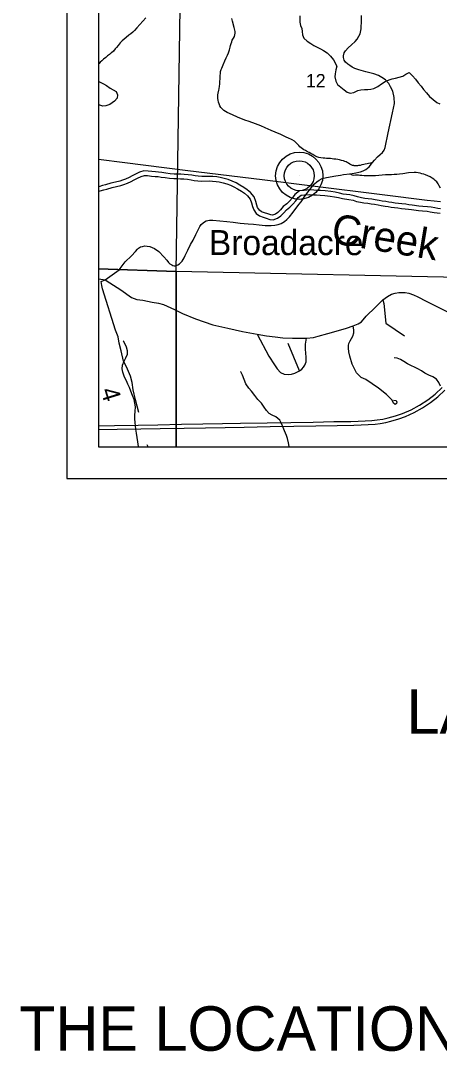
# Model space of a CAD drawing. Extents: x -19 to 40.8, y -1.8 to 26.1.
# Drawn here: x 1.854 to 3.175, y 12.195 to 15.443 of the extents above; entities that cross this region are included whole.
import ezdxf

# ---------------------------------------------------------------- set-up
doc = ezdxf.new("R2010")
doc.units = 0
for name, color, linetype in [('Default', 7, 'Continuous'), ('GM_X_Corporation', 7, 'Continuous'), ('GM_X_Corporation_Text', 7, 'Continuous'), ('GM_X_Interchange_Ramps', 7, 'Continuous'), ('GM_X_Major_River', 7, 'Continuous'), ('GM_X_Minor_River', 7, 'Continuous'), ('GM_X_Rail_Line', 7, 'Continuous'), ('GM_X_Section', 7, 'Continuous'), ('GM_X_Section_Text', 7, 'Continuous'), ('GM_X_State_Route', 7, 'Continuous'), ('GM_X_Township_Road', 7, 'Continuous'), ('GM_X_Township_Road_Text', 7, 'Continuous'), ('GM_X_Unincorporated', 7, 'Continuous'), ('RW_P_Text', 7, 'Continuous'), ('SH_Data', 7, 'Continuous'), ('SH_Text', 7, 'Continuous')]:
    doc.layers.add(name, color=color, linetype=linetype)

msp = doc.modelspace()

# ---------------------------------------------------------------- linework, layer by layer
at = {"layer": 'Default'}
for points in [[(2.1, 15.9023), (2.1, 14.6614), (2.3446, 14.653), (2.3634, 15.8992)], [(2.1, 14.6614), (2.1, 14.1), (2.3441, 14.1), (2.3446, 14.653)], [(2.3441, 14.1), (3.3277, 14.1), (3.3355, 14.6314), (2.3446, 14.653)]]:
    msp.add_lwpolyline(points, close=True, dxfattribs=at)
at = {"layer": 'GM_X_Corporation'}
for points in [[(2.121, 14.6264), (2.1357, 14.6167), (2.17, 14.5947), (2.2039, 14.5709), (2.2208, 14.5646), (2.2394, 14.5617), (2.2688, 14.5555), (2.2883, 14.5526), (2.304, 14.5485), (2.3396, 14.5331), (2.364, 14.5199), (2.4051, 14.5034), (2.4596, 14.484), (2.5077, 14.4735), (2.5535, 14.464), (2.5999, 14.4547), (2.6298, 14.4503), (2.6563, 14.4467), (2.6809, 14.4438), (2.7117, 14.4425), (2.7398, 14.4421), (2.7556, 14.4429), (2.7779, 14.4447), (2.7924, 14.4485), (2.8226, 14.457), (2.8418, 14.4629), (2.8817, 14.4737), (2.9029, 14.4813), (2.9188, 14.4872), (2.9294, 14.4941), (2.944, 14.5115), (2.973, 14.5401), (2.9958, 14.563), (3.0106, 14.5741), (3.0239, 14.5811), (3.0352, 14.5841), (3.0467, 14.5865), (3.0569, 14.5868), (3.0664, 14.5863), (3.0782, 14.5839), (3.0926, 14.5791), (3.1067, 14.5725), (3.1327, 14.5595)], [(3.1327, 14.5595), (3.1497, 14.5509), (3.1941, 14.5287), (3.2186, 14.5153), (3.2302, 14.5078), (3.2401, 14.5), (3.259, 14.4832), (3.2832, 14.4611), (3.3009, 14.4443), (3.314, 14.4321), (3.3181, 14.4282)]]:
    msp.add_lwpolyline(points, dxfattribs=at)
at = {"layer": 'GM_X_Interchange_Ramps'}
msp.add_lwpolyline([(3.1777, 14.8723), (3.1582, 14.8739), (3.1359, 14.8761), (2.9942, 14.8937), (2.7743, 14.9212), (2.624, 14.9399), (2.3727, 14.9713), (2.1822, 14.9952), (2.1, 15.0054)], dxfattribs=at)
at = {"layer": 'GM_X_Major_River'}
msp.add_line((2.7326, 14.9543), (2.7326, 14.9543), dxfattribs=at)
at = {"layer": 'GM_X_Rail_Line'}
for points in [[(2.9636, 14.9961), (2.9697, 15.0038), (2.9791, 15.0139), (2.9879, 15.0215), (2.995, 15.0271), (3.0008, 15.0349), (3.0036, 15.043), (3.0134, 15.0892), (3.0266, 15.1524), (3.0329, 15.1816), (3.0318, 15.2011), (3.0273, 15.2206), (3.0205, 15.234), (3.0148, 15.2445), (3.0042, 15.2561), (2.9934, 15.2641), (2.9825, 15.2697), (2.9674, 15.2754), (2.9431, 15.2821), (2.9211, 15.2877), (2.9081, 15.2924), (2.8998, 15.2967), (2.8918, 15.3018), (2.8854, 15.3055), (2.8788, 15.3117), (2.8748, 15.3183), (2.8725, 15.3268), (2.8725, 15.3325), (2.8742, 15.3411), (2.8785, 15.348), (2.8872, 15.3576), (2.8979, 15.3671), (2.9085, 15.3769), (2.9149, 15.3847), (2.9209, 15.3936), (2.9248, 15.4017), (2.9257, 15.4071), (2.9282, 15.4173), (2.9282, 15.4243), (2.9285, 15.4367), (2.9292, 15.4595)], [(2.892, 14.9606), (2.9063, 14.9627), (2.9256, 14.9664), (2.9345, 14.9698), (2.9427, 14.9744), (2.9527, 14.9825), (2.9636, 14.9961)], [(2.7156, 14.8423), (2.7229, 14.8526), (2.731, 14.8641), (2.7382, 14.8726), (2.7507, 14.89), (2.7741, 14.9213), (2.7804, 14.9289), (2.7876, 14.9353), (2.7959, 14.9408), (2.8049, 14.9452), (2.8185, 14.9489), (2.8478, 14.9536), (2.8632, 14.956)], [(2.8632, 14.956), (2.8722, 14.9577), (2.892, 14.9606)], [(2.121, 14.6264), (2.165, 14.6577), (2.1836, 14.6829), (2.2039, 14.7024), (2.2163, 14.7152), (2.2223, 14.7227), (2.226, 14.7261), (2.2323, 14.7298), (2.2383, 14.7318), (2.2453, 14.733), (2.2531, 14.7326), (2.2613, 14.7313), (2.269, 14.7286), (2.2761, 14.7253), (2.2896, 14.7159), (2.3057, 14.6991), (2.315, 14.6884), (2.3201, 14.6811), (2.3248, 14.6764), (2.3305, 14.6734), (2.3344, 14.6718), (2.3383, 14.6708), (2.342, 14.6709), (2.3455, 14.6717), (2.35, 14.6732), (2.3546, 14.6762), (2.3587, 14.6805), (2.3629, 14.6856), (2.3694, 14.6953), (2.3731, 14.7029), (2.3813, 14.72), (2.3902, 14.7376), (2.3977, 14.7514), (2.4061, 14.7693), (2.4128, 14.7821), (2.4191, 14.7944), (2.4236, 14.8004), (2.4294, 14.8059), (2.4336, 14.8093), (2.4391, 14.8118), (2.4442, 14.8135), (2.4497, 14.8144), (2.4601, 14.8145), (2.4818, 14.8122), (2.5044, 14.8098), (2.5244, 14.8081), (2.5461, 14.8052), (2.5714, 14.8028), (2.5882, 14.8015), (2.6062, 14.7998), (2.6251, 14.7978), (2.6437, 14.7972), (2.6558, 14.7983), (2.6658, 14.8005), (2.6754, 14.8041), (2.6864, 14.8106), (2.6935, 14.8162), (2.7022, 14.8246), (2.7139, 14.8399), (2.7156, 14.8423)], [(2.1, 14.6297), (2.1002, 14.6297), (2.121, 14.6264)]]:
    msp.add_lwpolyline(points, dxfattribs=at)
at = {"layer": 'GM_X_Section'}
for points in [[(2.7342, 15.4581), (2.7344, 15.4384), (2.7367, 15.4278), (2.7406, 15.4183), (2.7422, 15.4084), (2.7431, 15.3982), (2.7469, 15.3876), (2.7577, 15.3781), (2.7687, 15.371), (2.7787, 15.3642), (2.789, 15.3594), (2.8, 15.3542), (2.8096, 15.3485), (2.821, 15.3414), (2.8314, 15.3316), (2.8402, 15.3199), (2.8507, 15.2995), (2.8481, 15.288), (2.8455, 15.2755), (2.8449, 15.266), (2.848, 15.2523), (2.853, 15.2417), (2.8641, 15.2334), (2.8741, 15.2252), (2.884, 15.218), (2.8935, 15.2143), (2.9049, 15.2171), (2.917, 15.2232), (2.9273, 15.2252), (2.9383, 15.2264), (2.9485, 15.2258), (2.9584, 15.227), (2.9679, 15.2297), (2.98, 15.2351), (2.9921, 15.244), (3.0038, 15.2517), (3.0159, 15.2567), (3.0254, 15.2594), (3.0364, 15.2618), (3.0477, 15.2646), (3.0591, 15.2684), (3.0693, 15.2742), (3.0795, 15.2793), (3.0895, 15.2687), (3.0991, 15.2581), (3.1079, 15.2472), (3.1171, 15.237), (3.1248, 15.2264), (3.134, 15.2151), (3.1436, 15.2045), (3.1551, 15.1944), (3.1662, 15.1849), (3.1757, 15.1805)], [(2.1, 15.2513), (2.103, 15.2502), (2.1149, 15.2435), (2.1252, 15.2382), (2.1359, 15.2303), (2.1454, 15.2251), (2.1554, 15.2198), (2.1596, 15.2088), (2.1582, 15.1986), (2.1495, 15.189), (2.1348, 15.1786), (2.1223, 15.1743), (2.1128, 15.1739), (2.1033, 15.1765), (2.1, 15.1777)], [(2.9285, 14.885), (2.9167, 14.8874), (2.9062, 14.8907), (2.8917, 14.8938), (2.8713, 14.8967), (2.8591, 14.8995), (2.8461, 14.9022), (2.8321, 14.9045), (2.8147, 14.9063), (2.7999, 14.9074), (2.7881, 14.908), (2.7785, 14.9087), (2.7655, 14.9098), (2.7481, 14.9081), (2.7337, 14.9064), (2.7185, 14.8955), (2.7105, 14.8838), (2.7024, 14.8746), (2.6932, 14.8659), (2.6824, 14.8574), (2.6732, 14.8468), (2.6651, 14.8386), (2.6578, 14.8337), (2.6487, 14.8301), (2.6431, 14.8307), (2.6333, 14.8338), (2.6233, 14.8374), (2.6141, 14.8408), (2.6073, 14.8458), (2.6015, 14.8539), (2.5987, 14.8611), (2.596, 14.8727), (2.5905, 14.8876), (2.5793, 14.9011), (2.5683, 14.9102), (2.5579, 14.9175), (2.5454, 14.9251), (2.5332, 14.9318), (2.5209, 14.9374), (2.5083, 14.9424), (2.4959, 14.9456), (2.4833, 14.9486), (2.4728, 14.9506), (2.4599, 14.9518), (2.4497, 14.9521), (2.4251, 14.9519), (2.4136, 14.9525), (2.4039, 14.9538), (2.3942, 14.9556), (2.3823, 14.9576), (2.3698, 14.9583), (2.3588, 14.9589), (2.3477, 14.9597), (2.3379, 14.9596), (2.3253, 14.9605), (2.3115, 14.9627), (2.2992, 14.964), (2.2891, 14.966), (2.2789, 14.9663), (2.2678, 14.9673), (2.2558, 14.9687), (2.243, 14.9696), (2.2292, 14.9654), (2.2166, 14.9594), (2.2058, 14.9535), (2.1965, 14.9488), (2.1851, 14.9437), (2.1755, 14.9402), (2.1665, 14.9377), (2.1528, 14.9345), (2.1389, 14.9305), (2.1221, 14.9259), (2.1123, 14.9235), (2.1008, 14.9198), (2.1, 14.9195)], [(2.1, 14.9046), (2.1052, 14.9063), (2.1162, 14.9098), (2.1257, 14.9122), (2.1427, 14.9169), (2.1564, 14.9208), (2.17, 14.9239), (2.1799, 14.9267), (2.1905, 14.9305), (2.2026, 14.9359), (2.2124, 14.941), (2.223, 14.9468), (2.2344, 14.9522), (2.2446, 14.9553), (2.2545, 14.9546), (2.2663, 14.9532), (2.2781, 14.9521), (2.2876, 14.9518), (2.2971, 14.95), (2.3096, 14.9486), (2.3237, 14.9464), (2.3374, 14.9454), (2.3473, 14.9455), (2.3579, 14.9448), (2.3689, 14.9441), (2.3807, 14.9434), (2.3917, 14.9416), (2.4016, 14.9398), (2.4123, 14.9384), (2.4248, 14.9377), (2.4495, 14.9379), (2.459, 14.9376), (2.4708, 14.9366), (2.4803, 14.9347), (2.4925, 14.9318), (2.5039, 14.9288), (2.5154, 14.9244), (2.5268, 14.9191), (2.5383, 14.9128), (2.5501, 14.9056), (2.5596, 14.8989), (2.5692, 14.891), (2.578, 14.8804), (2.5823, 14.8687), (2.5851, 14.8569), (2.589, 14.8471), (2.597, 14.8357), (2.6074, 14.8282), (2.6184, 14.8241), (2.6287, 14.8204), (2.6401, 14.8167), (2.6508, 14.8156), (2.6644, 14.8211), (2.6742, 14.8276), (2.6836, 14.8372), (2.6923, 14.8471), (2.7025, 14.8552), (2.7127, 14.8648), (2.7217, 14.8751), (2.7288, 14.8854), (2.739, 14.8927), (2.7496, 14.8939), (2.7656, 14.8956), (2.7774, 14.8945), (2.7873, 14.8939), (2.799, 14.8932), (2.8135, 14.8922), (2.8302, 14.8904), (2.8435, 14.8882), (2.8561, 14.8857), (2.8686, 14.8827), (2.8892, 14.8799), (2.9025, 14.8769), (2.9132, 14.8736), (2.9257, 14.871)], [(3.1781, 14.8504), (3.1695, 14.8513), (3.1604, 14.8527), (3.1482, 14.8549), (3.1376, 14.8564), (3.1221, 14.8575), (3.1101, 14.8588), (3.0887, 14.8617), (3.0785, 14.8628), (3.0683, 14.8642), (3.0565, 14.8656), (3.0457, 14.8671), (3.0347, 14.8681), (3.025, 14.8695), (3.0152, 14.8713), (3.0055, 14.8728), (2.9939, 14.8745), (2.9842, 14.8763), (2.9721, 14.8786), (2.9615, 14.8801), (2.9503, 14.8815), (2.939, 14.8829), (2.9285, 14.885)], [(2.9257, 14.871), (2.9368, 14.8688), (2.9486, 14.8674), (2.9596, 14.866), (2.9699, 14.8645), (2.9817, 14.8624), (2.9915, 14.8605), (3.0033, 14.8587), (3.0128, 14.8573), (3.0227, 14.8555), (3.033, 14.854), (3.044, 14.853), (3.0547, 14.8515), (3.0665, 14.8501), (3.0767, 14.8487), (3.087, 14.8476), (3.1083, 14.8448), (3.1209, 14.8433), (3.1361, 14.8423), (3.146, 14.8409), (3.1581, 14.8387), (3.1676, 14.8372), (3.1771, 14.8362)], [(2.2264, 14.1), (2.2261, 14.1016), (2.224, 14.1157), (2.2216, 14.1297), (2.2193, 14.143), (2.2173, 14.1552), (2.216, 14.1658), (2.2148, 14.1772), (2.2143, 14.1886), (2.2146, 14.2), (2.2153, 14.211), (2.2159, 14.2258), (2.2146, 14.238), (2.2119, 14.249), (2.2065, 14.2618), (2.2014, 14.2759), (2.1971, 14.2865), (2.1917, 14.2975), (2.1875, 14.3084), (2.182, 14.3198), (2.1758, 14.3349), (2.1738, 14.3456), (2.1753, 14.3577), (2.1808, 14.3699), (2.1853, 14.3806), (2.1905, 14.3921), (2.1908, 14.4027), (2.1877, 14.4137), (2.1838, 14.4236), (2.178, 14.4334), (2.1773, 14.4345)], [(3.1784, 14.2909), (3.1734, 14.3026), (3.1657, 14.3128), (3.1542, 14.3211), (3.1416, 14.3259), (3.1286, 14.3327), (3.1179, 14.3394), (3.1069, 14.3462), (3.0962, 14.3514), (3.0867, 14.3555), (3.0745, 14.3611), (3.0622, 14.3686), (3.0519, 14.375), (3.042, 14.3798), (3.0321, 14.3809)], [(2.7011, 14.1), (2.701, 14.1012), (2.6986, 14.113), (2.6958, 14.1259), (2.6927, 14.1357), (2.6865, 14.1501), (2.6818, 14.1611), (2.6768, 14.174), (2.671, 14.1838), (2.6591, 14.1944), (2.6473, 14.2), (2.6374, 14.2048), (2.6289, 14.215), (2.6224, 14.2252), (2.6132, 14.2381), (2.6024, 14.2494), (2.5925, 14.2615), (2.5817, 14.2755), (2.5733, 14.2853), (2.564, 14.2981), (2.5586, 14.3121), (2.5532, 14.3258), (2.5481, 14.3368), (2.5477, 14.3371)]]:
    msp.add_lwpolyline(points, dxfattribs=at)
at = {"layer": 'GM_X_State_Route'}
for p, q in [((2.7338, 14.34), (2.6979, 14.426)), ((2.2559, 14.1), (2.2534, 14.1067))]:
    msp.add_line(p, q, dxfattribs=at)
msp.add_lwpolyline([(2.1, 15.8991), (2.1, 14.1), (4.3215, 14.1), (4.3262, 14.3024), (4.3261, 14.4335), (4.3369, 14.8581), (4.3371, 14.8653), (4.3373, 14.8703), (4.3441, 15.1043), (4.3494, 15.3211), (4.3628, 15.868), (3.9893, 15.872), (3.7032, 15.8784), (3.0926, 15.8861), (2.1833, 15.8974)], close=True, dxfattribs=at)
for points in [[(2.2483, 15.4516), (2.2389, 15.4412), (2.2297, 15.4306), (2.2202, 15.4199), (2.2128, 15.412), (2.2077, 15.4065), (2.2015, 15.4016), (2.1952, 15.397), (2.1864, 15.39), (2.1806, 15.3851), (2.174, 15.379), (2.1683, 15.3726), (2.1615, 15.3649), (2.1567, 15.3586), (2.1521, 15.3537), (2.1464, 15.3471), (2.1406, 15.3418), (2.1386, 15.3402), (2.1372, 15.3391)], [(2.9047, 14.9861), (2.9028, 14.9864), (2.9009, 14.9868), (2.896, 14.9887), (2.8919, 14.991), (2.8875, 14.9934), (2.884, 14.996), (2.8806, 14.9976), (2.8767, 14.9993), (2.8721, 15.0008), (2.8662, 15.0024), (2.8596, 15.0039), (2.8541, 15.0053), (2.8479, 15.0063), (2.8417, 15.0068), (2.8363, 15.0075), (2.8308, 15.0081), (2.8255, 15.0083), (2.8189, 15.0088), (2.8132, 15.0094), (2.8079, 15.0094), (2.8011, 15.0103), (2.7949, 15.0118), (2.7881, 15.0143), (2.7819, 15.0171), (2.7756, 15.0209), (2.769, 15.0242), (2.7643, 15.0272), (2.7584, 15.0299), (2.7525, 15.0338), (2.7472, 15.0363), (2.7391, 15.0418), (2.7347, 15.0453), (2.7314, 15.0494), (2.727, 15.0541), (2.7226, 15.0584), (2.7173, 15.0628), (2.7105, 15.0672), (2.7056, 15.0695), (2.7006, 15.0721), (2.6898, 15.0765), (2.6744, 15.084), (2.6564, 15.0917), (2.6441, 15.0971), (2.6254, 15.1051), (2.6111, 15.1112), (2.5951, 15.1176), (2.5751, 15.1249), (2.5608, 15.1297), (2.5377, 15.1393), (2.5221, 15.1462), (2.5052, 15.1539), (2.495, 15.16), (2.4898, 15.1649), (2.4858, 15.1697), (2.4827, 15.1748), (2.4801, 15.1805), (2.4781, 15.1862), (2.4768, 15.1921), (2.4761, 15.1981), (2.4759, 15.2044), (2.4763, 15.2095), (2.4774, 15.215), (2.4792, 15.2238), (2.4805, 15.228), (2.4816, 15.2361), (2.4823, 15.2427), (2.4825, 15.251), (2.4829, 15.2601), (2.4832, 15.2699), (2.4838, 15.2761), (2.4845, 15.2827), (2.4864, 15.2888), (2.4887, 15.2933), (2.4931, 15.304), (2.4983, 15.3163), (2.5023, 15.3258), (2.5062, 15.3346), (2.5096, 15.3421), (2.5126, 15.3511), (2.5152, 15.3597), (2.5159, 15.3649), (2.5175, 15.3706), (2.5199, 15.3763), (2.5214, 15.3812), (2.5249, 15.3878), (2.528, 15.3933), (2.5296, 15.3984), (2.5309, 15.4034), (2.5307, 15.4084), (2.5298, 15.4131), (2.5274, 15.4216), (2.5223, 15.441), (2.5199, 15.4494)], [(2.1372, 15.3391), (2.1338, 15.3364), (2.1279, 15.3319), (2.1224, 15.3269), (2.1156, 15.3216), (2.1098, 15.3166), (2.1052, 15.3126), (2.1011, 15.3084), (2.1, 15.3071)], [(2.892, 14.9606), (2.9063, 14.9627), (2.9256, 14.9664), (2.9345, 14.9698), (2.9427, 14.9744), (2.9527, 14.9825), (2.9636, 14.9961)], [(2.9636, 14.9961), (2.9569, 14.9936), (2.9512, 14.9925), (2.9466, 14.9916), (2.9409, 14.9905), (2.936, 14.9894), (2.9305, 14.9883), (2.9248, 14.987), (2.9193, 14.9866), (2.9165, 14.9859), (2.9142, 14.9857), (2.91, 14.9858), (2.9056, 14.9859), (2.9047, 14.9861)], [(3.1785, 14.9149), (3.1744, 14.9224), (3.1709, 14.929), (3.1662, 14.9351), (3.1618, 14.9395), (3.157, 14.9431), (3.1517, 14.947), (3.1458, 14.9509), (3.1385, 14.9538), (3.1311, 14.9567), (3.1253, 14.9589), (3.1196, 14.9608), (3.1139, 14.9624), (3.1074, 14.9637), (3.1014, 14.9646), (3.0948, 14.965), (3.0776, 14.9634), (3.0589, 14.9606), (3.0486, 14.9593), (3.0401, 14.9586), (3.0317, 14.9582), (3.0231, 14.9575), (3.0046, 14.9569), (2.9735, 14.9543), (2.9609, 14.9538), (2.9521, 14.954), (2.9449, 14.9538), (2.9376, 14.9543), (2.9303, 14.9549), (2.9242, 14.9554), (2.9196, 14.956), (2.9149, 14.9562), (2.9097, 14.9556), (2.904, 14.9554), (2.8996, 14.9562), (2.8965, 14.958), (2.892, 14.9606)], [(2.227, 14.2086), (2.2158, 14.2482), (2.2088, 14.28), (2.2054, 14.3027), (2.2002, 14.3227), (2.1883, 14.352), (2.1786, 14.3701), (2.1709, 14.4022), (2.1652, 14.4263), (2.1611, 14.4464), (2.1535, 14.4679), (2.1123, 14.5975), (2.1098, 14.6085), (2.1077, 14.6206), (2.121, 14.6264)], [(2.9958, 14.563), (2.9994, 14.5517), (3.0054, 14.4893), (3.0645, 14.4501)], [(2.5999, 14.4547), (2.637, 14.3858), (2.655, 14.3589), (2.6635, 14.3462), (2.674, 14.3344), (2.6851, 14.329), (2.6985, 14.3277), (2.7078, 14.3289), (2.7191, 14.3326), (2.7338, 14.34), (2.7406, 14.3451), (2.7465, 14.3515), (2.7504, 14.3578), (2.7548, 14.3684), (2.7547, 14.3826), (2.7525, 14.4076), (2.752, 14.424), (2.7556, 14.4429)], [(3.03, 14.2469), (3.0381, 14.2461), (3.0405, 14.2411), (3.0396, 14.2371), (3.0355, 14.2336), (3.0297, 14.2377), (3.0254, 14.2475), (3.008, 14.2646), (2.9825, 14.2854), (2.9424, 14.312), (2.9282, 14.3189), (2.9131, 14.3336), (2.8995, 14.3606), (2.8921, 14.3858), (2.889, 14.3998), (2.8878, 14.4109), (2.8877, 14.4198), (2.8894, 14.426), (2.8934, 14.4344), (2.9013, 14.4489), (2.9046, 14.4595), (2.9053, 14.4674), (2.9029, 14.4813)]]:
    msp.add_lwpolyline(points, dxfattribs=at)
at = {"layer": 'GM_X_Township_Road'}
for points in [[(2.1, 14.1666), (2.1498, 14.1675), (2.2248, 14.1687), (2.2868, 14.1698), (2.3617, 14.1711), (2.4284, 14.1723), (2.4911, 14.1735), (2.5478, 14.1745), (2.631, 14.1757), (2.7058, 14.177), (2.7762, 14.1782), (2.8419, 14.1794), (2.8952, 14.1801), (2.9182, 14.1806), (2.9406, 14.1815), (2.9619, 14.1829), (2.9782, 14.1847), (2.9958, 14.1877), (3.0131, 14.1913), (3.0365, 14.1977), (3.0588, 14.2054), (3.0859, 14.2171), (3.1123, 14.2315), (3.1379, 14.2482), (3.1614, 14.2665), (3.1834, 14.2869)], [(2.1, 14.1547), (2.1585, 14.1556), (2.2334, 14.1569), (2.2944, 14.1579), (2.3699, 14.1591), (2.4369, 14.1604), (2.4985, 14.1614), (2.5586, 14.1623), (2.6411, 14.1639), (2.7161, 14.1652), (2.7852, 14.1664), (2.8524, 14.1674), (2.9049, 14.1684), (2.928, 14.1689), (2.9504, 14.1699), (2.9722, 14.1719), (2.9882, 14.174), (3.0057, 14.1771), (3.021, 14.1807), (3.0465, 14.1881), (3.0679, 14.1961), (3.0955, 14.2084), (3.1212, 14.2227), (3.1468, 14.2395), (3.17, 14.2579), (3.192, 14.2783)]]:
    msp.add_lwpolyline(points, dxfattribs=at)
at = {"layer": 'GM_X_Unincorporated'}
for radius in [0.0744, 0.0472]:
    msp.add_circle((2.7326, 14.9543), radius, dxfattribs=at)
at = {"layer": 'RW_P_Text'}
msp.add_lwpolyline([(2.3634, 15.8992), (3.3595, 15.883), (3.3355, 14.6314), (2.3446, 14.653)], close=True, dxfattribs=at)
at = {"layer": 'SH_Data'}
for p, q in [((2, 21), (2, 14)), ((2.1, 20.9), (2.1, 14.1)), ((2.1, 14.1), (8.9, 14.1)), ((2.1, 14.1), (2.1, 14.1)), ((2, 14), (9, 14))]:
    msp.add_line(p, q, dxfattribs=at)

# ---------------------------------------------------------------- texts
at = {"layer": 'GM_X_Corporation_Text'}
msp.add_text('Broadacre', height=0.07898, rotation=0, dxfattribs=at).set_placement((2.4478, 14.7042))
at = {"layer": 'GM_X_Minor_River'}
msp.add_text('Creek', height=0.0947, rotation=350.5621, dxfattribs=at).set_placement((2.8298, 14.7428))
at = {"layer": 'GM_X_Section_Text'}
msp.add_text('12', height=0.04186, rotation=0, dxfattribs=at).set_placement((2.7536, 15.2329))
at = {"layer": 'GM_X_Township_Road_Text'}
msp.add_text('4', height=0.0568, rotation=287.1793, dxfattribs=at).set_placement((2.1053, 14.2782))
at = {"layer": 'SH_Text'}
for s, p in [('LATITUDE:  ', (3.071, 13.1958)), ('THE LOCATION OF THE UNDERGROUND UTILITIES SHOWN ON THE PLANS ARE OBTAINED FROM THE', (1.8496, 12.197))]:
    msp.add_text(s, height=0.14, dxfattribs=at).set_placement(p)

doc.saveas('drawing.dxf')
